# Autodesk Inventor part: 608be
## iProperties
Shininess: 64.0
Length Units: 11269
Angle Units: 11279
Time Units: 11290
Mass Units: 11283
Length Display Precision: 3
Angle Display Precision: 2
Compacted: True
Part Number: 608be
Document SubType Name: Modeling
Created: 2004-09
Material: Par défaut
Density: 1 g/cm^3
Density: 0.0
Volumn: 0.0
Area: 0.0
PropertySet Name: Model Information
Control State: 0
Master: False
Checked Out: False
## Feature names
1. Révolution1 [Revolution]
